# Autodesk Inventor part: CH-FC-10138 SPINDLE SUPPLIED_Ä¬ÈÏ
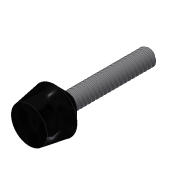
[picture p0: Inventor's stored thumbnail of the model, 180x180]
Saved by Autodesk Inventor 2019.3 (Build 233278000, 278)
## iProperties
Created: 2010-06
Part Number: CH-FC-10138 SPINDLE SUPPLIED_Ä¬ÈÏ
Material: Ogólny
Document SubType Name: Modeling
Designer: CADENGINEERING4
Density: 1 g/cm^3
Appearance: Domyślna
Author: CADENGINEERING4
Revision Number: ÈÎºÎ
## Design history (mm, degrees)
feature "NONE"
node "Bryła1"
